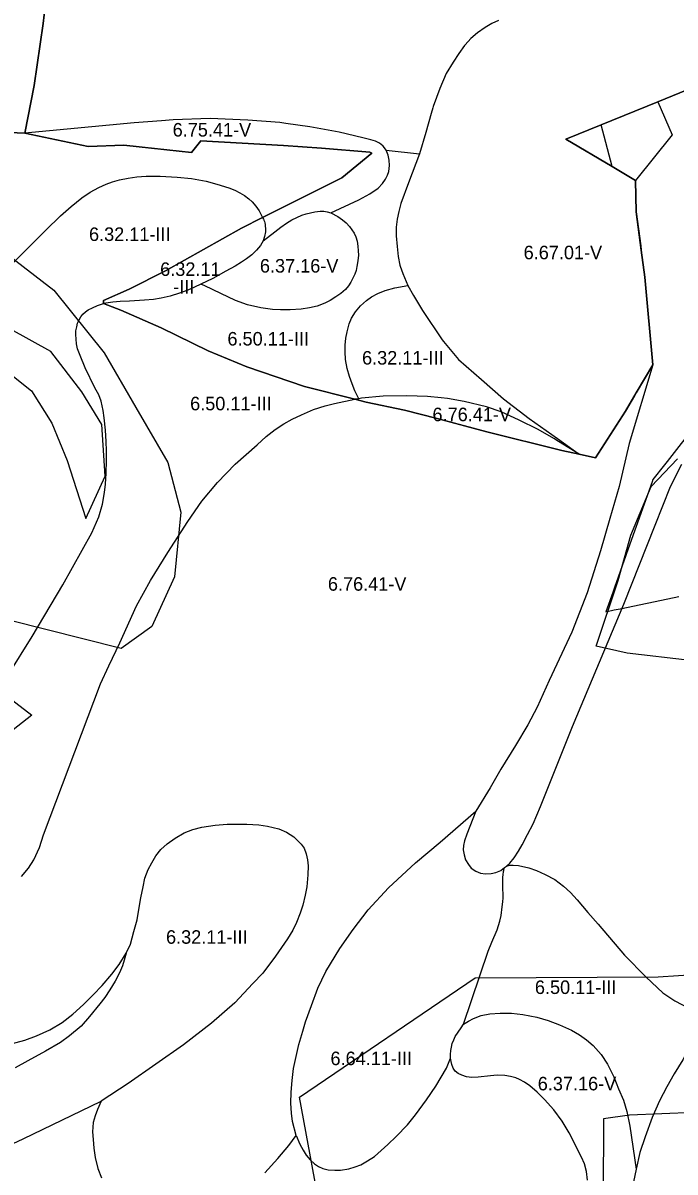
# Model space of a CAD drawing. Extents: x -555156 to -540209, y -1046851 to -1035695.
# Drawn here: x -544168 to -543686, y -1041405 to -1040556 of the extents above; entities that cross this region are included whole.
import ezdxf

# ---------------------------------------------------------------- set-up
doc = ezdxf.new("R2010")
doc.units = 0
for name, color, linetype in [('Vrstva 12', 7, 'Continuous'), ('Vrstva 27', 7, 'Continuous'), ('Vrstva 28', 7, 'Continuous'), ('Vrstva 29', 7, 'Continuous')]:
    doc.layers.add(name, color=color, linetype=linetype)

msp = doc.modelspace()

# ---------------------------------------------------------------- linework, layer by layer
at = {"layer": 'Vrstva 12'}
for points in [[(-543648.44, -1040824.55), (-543691.97, -1040880.16), (-543693.82, -1040882.53), (-543702.32, -1040893.39), (-543702.91, -1040895.06), (-543720.55, -1040944.72), (-543722.26, -1040949.53), (-543730.66, -1040973.17), (-543732.03, -1040977.02), (-543737.03, -1040991.11), (-543730.9, -1040989.84), (-543726.55, -1040988.94), (-543686.62, -1040980.68), (-543683.27, -1040979.99)], [(-543671.97, -1041361.22), (-543719.58, -1041363.23), (-543738.950827, -1041365.94664), (-543738.95, -1041369.67), (-543738.97, -1041384.97), (-543739.29, -1041421.11)]]:
    msp.add_lwpolyline(points, dxfattribs=at)
at = {"layer": 'Vrstva 28'}
for points in [[(-544166.22, -1040637.59), (-544159.37, -1040602.39), (-544152.78, -1040556.39), (-544148.25, -1040518.25), (-544148.05, -1040516.52), (-544147.1, -1040509.05), (-544119.61, -1040511.85), (-544114.36, -1040467.79), (-544109.21, -1040427.07), (-544107.28, -1040390.92), (-544084.37, -1040386.84), (-544033.06, -1040401.65), (-543986.48, -1040373.41), (-543990.67, -1040372.14), (-543961.4, -1040311.25), (-543946.79, -1040291.41)], [(-544148.45, -1040519.91), (-544152.78, -1040556.39), (-544159.37, -1040602.39), (-544166.22, -1040637.59), (-544194.81, -1040636.28)], [(-543816.51, -1040554.2), (-543821.29, -1040556.44), (-543826.22, -1040559.43), (-543831.9, -1040563.46), (-543836.83, -1040567.65), (-543840.95, -1040572.17), (-543841.46, -1040572.73), (-543845.64, -1040578.56), (-543849.97, -1040585.13), (-543855.2, -1040593.5), (-543859.83, -1040604.41), (-543864.61, -1040617.71), (-543864.93, -1040618.82), (-543866.15, -1040623.11), (-543870.1, -1040637), (-543874.8, -1040652.69)], [(-543702.42, -1040808.65), (-543708.38, -1040743.94), (-543710.96, -1040724.1), (-543714.65, -1040695.64), (-543715.21, -1040672.48), (-543732.41, -1040662.28), (-543766.58, -1040642.03), (-543740.61, -1040631.41), (-543698.83, -1040614.32), (-543593.47, -1040571.22), (-543590.56, -1040569.96), (-543587.92, -1040562.74), (-543571.38, -1040556.86), (-543563.03, -1040579.77)], [(-543593.47, -1040571.22), (-543698.83, -1040614.32), (-543740.61, -1040631.41), (-543766.58, -1040642.03), (-543732.41, -1040662.28), (-543715.21, -1040672.48), (-543714.65, -1040695.64), (-543711.4, -1040720.7), (-543710.96, -1040724.1), (-543708.38, -1040743.94), (-543702.42, -1040808.65), (-543714.73, -1040829.47), (-543715.98, -1040831.59), (-543722.63, -1040842.84), (-543744.71, -1040877.32), (-543756.76, -1040874.7)], [(-543910.66, -1040642.36), (-543916.57, -1040640.99), (-543934.09, -1040636.81), (-543955.78, -1040632.89), (-543973.45, -1040630.39), (-543978, -1040629.75), (-544001.53, -1040627.92), (-544029.5, -1040626.61), (-544056.68, -1040627.66), (-544065.45, -1040628.38), (-544085.44, -1040630.01), (-544166.22, -1040637.59)], [(-544297.7, -1040664.73), (-544298.67, -1040642.1), (-544267.15, -1040646.48), (-544246.26, -1040643.8), (-544216.62, -1040644.41), (-544194.81, -1040636.28), (-544166.22, -1040637.59)], [(-544166.22, -1040637.59), (-544119.59, -1040647.38), (-544093.27, -1040646.28), (-544043.13, -1040651.87), (-544036.41, -1040643.09), (-543975.26, -1040646.77), (-543947.29, -1040648.59), (-543911.39, -1040651.66), (-543910.01, -1040652.36), (-543932.13, -1040670.57), (-543990.72, -1040699.94)], [(-543990.71, -1040699.94), (-543932.13, -1040670.57), (-543910.01, -1040652.36), (-543911.39, -1040651.66), (-543947.29, -1040648.59), (-543975.26, -1040646.77), (-544036.41, -1040643.09), (-544043.13, -1040651.87), (-544068.2, -1040649.08), (-544093.27, -1040646.28), (-544119.59, -1040647.38), (-544166.22, -1040637.59)], [(-543899.3, -1040650.05), (-543900.69, -1040648.36), (-543901.69, -1040647.14), (-543903.46, -1040645.77), (-543904.77, -1040644.75), (-543907.24, -1040643.47), (-543910.66, -1040642.36)], [(-543940.17, -1040696.35), (-543919.71, -1040686.79), (-543911.49, -1040682.45), (-543905.28, -1040678.06), (-543902.12, -1040674.64), (-543899.9, -1040671.57), (-543898.36, -1040668.58), (-543897.51, -1040665.76), (-543896.91, -1040661.32), (-543897.08, -1040657.56), (-543897.94, -1040653.89), (-543899.3, -1040650.05)], [(-543899.3, -1040650.05), (-543874.8, -1040652.69)], [(-543874.8, -1040652.69), (-543882.91, -1040674.14), (-543888.66, -1040689.57), (-543890.15, -1040695.43), (-543891.2, -1040701.11), (-543892.09, -1040707.08), (-543892.09, -1040713.51), (-543891.35, -1040721.28), (-543890.45, -1040728.75), (-543889.26, -1040735.03), (-543888.98, -1040735.84), (-543887.17, -1040741.16), (-543883.28, -1040749.98)], [(-544176.07, -1040734.52), (-544150.81, -1040709.32), (-544139.86, -1040698.54), (-544132.11, -1040691.75), (-544124.12, -1040685.33), (-544118.06, -1040681.21), (-544111.52, -1040677.7), (-544106.32, -1040675.27), (-544101.47, -1040673.58), (-544096.39, -1040672), (-544089.97, -1040670.79), (-544083.67, -1040669.7), (-544076.65, -1040669.33), (-544066.23, -1040669.33), (-544053.88, -1040669.94), (-544043.1, -1040671.15), (-544032.32, -1040673.09), (-544024.57, -1040675.15), (-544015.61, -1040677.82), (-544011.3, -1040679.63), (-544007.49, -1040681.57), (-544003.96, -1040683.65), (-544000.85, -1040686), (-543998.36, -1040688.36), (-543995.73, -1040691.54), (-543993.31, -1040694.94), (-543990.72, -1040699.94)], [(-543990.18, -1040717.05), (-543981.69, -1040710.41), (-543977.16, -1040706.99), (-543972.91, -1040704.11), (-543969.06, -1040701.63), (-543965.5, -1040699.77), (-543961.65, -1040698.21), (-543958.38, -1040697.18), (-543955.36, -1040696.31), (-543952.19, -1040695.67), (-543948.14, -1040695.28), (-543945.41, -1040695.28), (-543943.06, -1040695.62), (-543940.17, -1040696.35)], [(-543940.17, -1040696.35), (-543935.12, -1040699.16), (-543931.54, -1040701.55), (-543928.95, -1040703.79), (-543926.41, -1040706.62), (-543924.71, -1040708.96), (-543923.1, -1040711.4), (-543921.78, -1040714.14), (-543920.81, -1040717.36), (-543920.23, -1040721.14), (-543919.99, -1040724.36), (-543919.94, -1040727.63), (-543920.33, -1040731.88), (-543921.01, -1040736.17), (-543921.61, -1040738.91), (-543922.44, -1040741.64), (-543923.95, -1040744.77), (-543925.51, -1040747.74), (-543927.17, -1040750.28), (-543929.56, -1040753.11), (-543932.83, -1040755.89), (-543936.68, -1040758.43), (-543940.73, -1040761.06), (-543944.78, -1040763.11), (-543950.3, -1040765.4), (-543956.02, -1040766.6), (-543962.17, -1040767.54), (-543970.36, -1040767.96)], [(-543990.72, -1040699.94), (-544006.25, -1040707.73), (-544062.36, -1040739.14), (-544089.23, -1040752.75), (-544108.19, -1040761.26), (-544108.27, -1040763.37)], [(-544108.27, -1040763.37), (-544108.19, -1040761.26), (-544089.23, -1040752.75), (-544062.36, -1040739.14), (-544006.25, -1040707.73), (-543990.71, -1040699.94)], [(-543990.71, -1040699.94), (-543990.13, -1040700.99), (-543989.82, -1040701.67), (-543989.71, -1040701.91), (-543989.26, -1040702.89), (-543989.04, -1040703.86), (-543988.82, -1040705.03), (-543988.68, -1040706.26), (-543988.65, -1040708), (-543988.65, -1040710.47), (-543989.24, -1040713.89), (-543990.18, -1040717.05)], [(-543990.18, -1040717.05), (-543992.15, -1040720.47), (-543995.13, -1040724.05), (-543998.55, -1040727.38), (-544002.56, -1040730.46), (-544006.27, -1040732.95), (-544010.97, -1040735.77), (-544017.8, -1040739.61), (-544027.36, -1040744.82), (-544036.21, -1040749.01)], [(-544036.21, -1040749.01), (-544040.9, -1040751.32), (-544046.02, -1040753.45), (-544052.08, -1040755.76), (-544058.91, -1040757.89), (-544065.65, -1040759.43), (-544071.29, -1040760.45), (-544077.86, -1040761.05), (-544089.04, -1040761.56), (-544095.87, -1040761.99), (-544101.25, -1040762.33)], [(-543970.36, -1040767.96), (-543977.53, -1040768.13), (-543983.42, -1040767.79), (-543991.87, -1040766.68), (-544001.77, -1040764.29), (-544010.73, -1040761.3), (-544021.57, -1040756.09), (-544033.44, -1040750.46), (-544036.21, -1040749.01)], [(-543918.25, -1040765.13), (-543913.99, -1040761.29), (-543910.23, -1040758.47), (-543905.62, -1040755.91), (-543900.16, -1040753.86), (-543893.08, -1040751.72), (-543883.28, -1040749.98)], [(-543883.28, -1040749.98), (-543879.25, -1040757.45), (-543872.68, -1040768.51), (-543857.99, -1040790.28), (-543857.15, -1040791.52), (-543845.91, -1040804.86), (-543828.92, -1040819.5)], [(-544196.12, -1041065.58), (-544160.88, -1041009.55), (-544138.26, -1040971.27), (-544116.85, -1040932.89), (-544111.56, -1040921.02), (-544108.95, -1040911.66), (-544107.5, -1040902.93), (-544106.77, -1040896.99), (-544106.17, -1040888.88), (-544105.92, -1040879.18), (-544105.92, -1040872.27), (-544106.17, -1040865.49), (-544106.65, -1040856.89), (-544107.74, -1040847.8), (-544108.35, -1040842.35), (-544109.92, -1040835.68), (-544111.62, -1040830.83), (-544114.52, -1040825.72), (-544121.65, -1040810.83), (-544125.38, -1040801.76), (-544127.32, -1040796.78), (-544128.08, -1040793.31), (-544128.5, -1040789.85), (-544128.64, -1040786.39), (-544128.64, -1040783.62), (-544128.01, -1040780.57), (-544127.32, -1040778.01), (-544126.21, -1040775.52), (-544124.97, -1040773.3), (-544123.45, -1040771.36), (-544121.58, -1040769.63), (-544119.42, -1040768.11), (-544116.27, -1040766.53), (-544112.63, -1040764.84), (-544108.27, -1040763.37)], [(-544101.25, -1040762.33), (-544108.27, -1040763.37)], [(-544108.27, -1040763.37), (-544095.39, -1040768.31)], [(-543922.54, -1040834.19), (-543959.63, -1040824.69), (-544002.2, -1040810.3), (-544030.94, -1040798.31), (-544065.53, -1040781.42), (-544095.39, -1040768.31), (-544108.27, -1040763.37)], [(-543919.6, -1040833.75), (-543920.66, -1040831.83), (-543922.5, -1040827.86), (-543924.46, -1040822.82), (-543926.51, -1040817.44), (-543928.13, -1040811.47), (-543929.33, -1040804.89), (-543929.67, -1040799.08), (-543929.61, -1040794.25), (-543929.18, -1040789.04), (-543928.24, -1040784.43), (-543926.79, -1040778.45), (-543925, -1040774.18), (-543922.01, -1040769.49), (-543918.25, -1040765.13)], [(-544095.39, -1040768.31), (-544065.53, -1040781.42), (-544030.94, -1040798.31), (-544002.2, -1040810.3), (-543959.63, -1040824.69), (-543922.49, -1040834.2)], [(-543922.49, -1040834.2), (-543914.18, -1040836.33), (-543885.98, -1040842.13), (-543861.85, -1040848.48), (-543825.12, -1040858.15), (-543769.53, -1040871.92), (-543756.76, -1040874.7), (-543744.71, -1040877.32), (-543722.63, -1040842.84), (-543714.73, -1040829.47), (-543702.42, -1040808.65)], [(-543702.42, -1040808.65), (-543719.92, -1040866.73)], [(-543828.92, -1040819.5), (-543812.71, -1040833.89), (-543793.89, -1040848.27), (-543772.96, -1040863.17), (-543756.76, -1040874.7)], [(-544168.82, -1041186.75), (-544163.61, -1041180.57), (-544159.74, -1041174.39), (-544155.5, -1041165.31), (-544152.59, -1041155.98), (-544110.4, -1041044.53), (-544104.37, -1041031.07), (-544096.1, -1041014.1), (-544083.81, -1040986.75), (-544073.43, -1040968.09), (-544060.71, -1040947.31), (-544045.88, -1040924.4), (-544035.49, -1040909.56), (-544024.05, -1040895.78), (-544010.91, -1040882.21), (-543994.8, -1040867.79), (-543987.98, -1040861.66), (-543981.32, -1040856.57), (-543974.9, -1040852.33), (-543968.85, -1040848.82), (-543962.06, -1040845.55), (-543953.1, -1040841.67), (-543944.38, -1040839), (-543937.48, -1040837.31), (-543922.49, -1040834.2)], [(-543919.6, -1040833.75), (-543922.54, -1040834.19)], [(-543756.76, -1040874.7), (-543769.53, -1040871.92), (-543825.12, -1040858.15), (-543859.1, -1040849.21), (-543861.85, -1040848.48), (-543885.98, -1040842.13), (-543914.18, -1040836.33), (-543922.54, -1040834.19)], [(-543772.11, -1040865.35), (-543775.52, -1040863.27), (-543787.17, -1040856.55), (-543801.07, -1040849.67), (-543814.36, -1040843.55), (-543825.41, -1040839.66), (-543841.84, -1040835.92), (-543854.09, -1040833.68), (-543858.8, -1040833.16), (-543868.88, -1040832.04), (-543884.11, -1040831.74), (-543901.74, -1040831.89), (-543917.64, -1040833.46), (-543919.6, -1040833.75)], [(-543719.92, -1040866.73), (-543727.34, -1040898.54), (-543734.12, -1040922.29), (-543741.11, -1040946.04), (-543750.87, -1040977.09), (-543762.32, -1041006.14), (-543779.06, -1041041.98), (-543787.96, -1041061.7), (-543794.75, -1041074.84), (-543803.92, -1041090.04), (-543814.82, -1041107.49), (-543822.57, -1041121.31), (-543833.11, -1041138.63)], [(-543756.76, -1040874.7), (-543772.11, -1040865.35)], [(-543810.54, -1041179.21), (-543808.12, -1041176.92), (-543804.93, -1041172.91), (-543801.68, -1041167.99), (-543798.91, -1041163.49), (-543795.04, -1041155.86), (-543790.92, -1041147.86), (-543785.39, -1041135.08), (-543761.66, -1041076.07), (-543723.84, -1040985.67), (-543700.74, -1040927.15), (-543689.29, -1040898.52), (-543681.03, -1040882.19)], [(-543965.9, -1041378.12), (-543968.7, -1041367.88), (-543969.43, -1041361.58), (-543969.92, -1041354.31), (-543969.55, -1041346.19), (-543968.83, -1041337.47), (-543967.74, -1041328.74), (-543965.92, -1041319.89), (-543963.86, -1041310.93), (-543961.07, -1041301.11), (-543958.89, -1041294.09), (-543954.57, -1041282.1), (-543949.91, -1041269.37), (-543943.98, -1041257.07), (-543933.59, -1041240.11), (-543923.84, -1041225.9), (-543912.61, -1041211.48), (-543897.56, -1041195.16), (-543877.85, -1041176.71), (-543859.62, -1041161.44), (-543833.11, -1041138.63)], [(-543833.11, -1041138.63), (-543839.88, -1041155.6)], [(-543993.5, -1041148.65), (-543986.96, -1041149.62), (-543978.72, -1041151.56), (-543973.03, -1041154.11), (-543967.7, -1041157.38), (-543962.13, -1041162.83), (-543960.09, -1041165.78), (-543958.43, -1041170.07), (-543957.39, -1041174.57), (-543957.05, -1041179.01), (-543957.25, -1041185.58), (-543958.02, -1041194.52), (-543959.12, -1041200.47), (-543961.06, -1041207.95), (-543963.05, -1041213.93), (-543965.71, -1041220.72), (-543968.25, -1041226.41), (-543972.25, -1041232.84), (-543981.09, -1041245.68), (-543990.54, -1041258.16), (-543997.8, -1041265.92), (-544011.13, -1041280.22), (-544028.32, -1041295.24), (-544049.2, -1041311.19), (-544089.89, -1041339.82), (-544109.81, -1041352.75)], [(-544091.46, -1041243.47), (-544088.31, -1041236.68), (-544085.77, -1041227.35), (-544083.22, -1041218.75), (-544082.03, -1041211.3), (-544080.69, -1041202.58), (-544079, -1041194.34), (-544077.55, -1041188.03), (-544075.12, -1041181.73), (-544072.58, -1041176.64), (-544069.43, -1041171.43), (-544065.8, -1041166.95), (-544061.2, -1041162.59), (-544055.38, -1041158.35), (-544048.72, -1041154.59), (-544042.3, -1041152.05), (-544035.64, -1041150.35), (-544025.83, -1041148.9), (-544016.87, -1041148.17), (-544009.73, -1041148.17), (-544002.34, -1041148.05), (-543993.5, -1041148.65)], [(-543839.88, -1041155.6), (-543841.61, -1041160.44), (-543842.37, -1041163.77), (-543842.44, -1041167.09), (-543841.89, -1041170.9), (-543840.71, -1041174.57), (-543838.71, -1041178.03), (-543836.7, -1041180.52), (-543833.24, -1041182.88), (-543829.85, -1041184.26), (-543825.97, -1041184.82), (-543821.82, -1041184.61), (-543818.5, -1041183.92), (-543814.83, -1041182.39), (-543811.92, -1041180.24)], [(-543842.17, -1041296.03), (-543823.96, -1041241.94), (-543821.4, -1041235.44), (-543817.53, -1041226.23), (-543815.52, -1041219.72), (-543814.55, -1041215.56), (-543813.65, -1041209.19), (-543813.17, -1041205.45), (-543813.04, -1041202.51), (-543813.16, -1041193.22), (-543813.12, -1041188.15), (-543812.9, -1041184.72), (-543812.82, -1041183.93), (-543812.76, -1041183.22), (-543812.61, -1041182.46), (-543812.45, -1041181.71), (-543812.27, -1041181.01), (-543811.92, -1041180.24)], [(-543811.92, -1041180.24), (-543810.54, -1041179.21)], [(-543810.54, -1041179.21), (-543809.67, -1041178.86), (-543808.93, -1041178.62), (-543808.19, -1041178.47), (-543807.49, -1041178.38), (-543806.6, -1041178.31), (-543805.56, -1041178.33)], [(-543805.56, -1041178.33), (-543801.54, -1041178.79), (-543794.15, -1041180.49), (-543788.46, -1041182.31), (-543781.92, -1041185.21), (-543774.9, -1041189.09), (-543768.48, -1041193.94), (-543763.27, -1041198.54), (-543758.31, -1041204), (-543750.56, -1041213.33), (-543742.85, -1041221.98), (-543723.35, -1041244.88), (-543707.45, -1041261.21), (-543695.16, -1041272.66), (-543686.26, -1041278.59), (-543675.24, -1041284.32), (-543662.75, -1041290.03)], [(-544179.12, -1041311.23), (-544166.41, -1041307.71), (-544157.57, -1041304.44), (-544147.76, -1041300.08), (-544138.8, -1041294.63), (-544130.92, -1041288.57), (-544122.93, -1041281.3), (-544115.92, -1041274.13), (-544109.26, -1041267.34), (-544102.11, -1041258.98), (-544096.54, -1041251.83), (-544091.46, -1041243.47)], [(-544091.46, -1041243.47), (-544093.01, -1041248.71), (-544094.18, -1041252.79), (-544096.33, -1041258.06), (-544099.65, -1041264.22), (-544103.6, -1041270.59), (-544107.33, -1041276.13), (-544110.79, -1041280.99), (-544118.42, -1041290.32), (-544124.72, -1041297.35), (-544133.2, -1041304.5), (-544140.05, -1041309.44), (-544150.95, -1041315.86), (-544164.16, -1041323.01), (-544173.48, -1041328.1)], [(-543842.17, -1041296.03), (-543838.6, -1041293.6), (-543834.96, -1041291.66), (-543829.15, -1041289.6), (-543822.85, -1041288.39), (-543815.1, -1041287.9), (-543806.74, -1041287.78), (-543798.39, -1041288.75)], [(-543798.39, -1041288.75), (-543788.09, -1041290.69), (-543779.74, -1041293.11), (-543771.26, -1041296.38), (-543762.54, -1041300.38), (-543756.61, -1041303.9), (-543751.52, -1041307.53), (-543746.55, -1041311.65), (-543740.5, -1041318.2), (-543735.9, -1041325.47), (-543731.29, -1041334.8), (-543727.69, -1041343.64), (-543724.06, -1041352), (-543721.76, -1041360.49), (-543719.34, -1041371.39), (-543714.76, -1041402.93)], [(-543662.75, -1041290.03), (-543673.29, -1041310.02), (-543680.19, -1041322.38), (-543686.61, -1041332.56), (-543691.99, -1041342.1), (-543697.44, -1041352.64), (-543703.01, -1041364.76), (-543708.22, -1041379.06), (-543712.09, -1041390.81), (-543714.76, -1041402.93)], [(-543851.78, -1041320.96), (-543851.78, -1041318.32), (-543851.71, -1041315.49), (-543851.23, -1041312.79), (-543850.54, -1041310.29), (-543849.5, -1041307.52), (-543848.32, -1041305.03), (-543846.24, -1041301.91), (-543844.1, -1041298.66), (-543842.17, -1041296.03)], [(-543965.9, -1041378.12), (-543963.26, -1041384.64), (-543960.71, -1041389), (-543958.41, -1041392.75), (-543955.44, -1041396.1), (-543952.39, -1041399.14), (-543949.49, -1041401.15), (-543946.1, -1041402.6), (-543942.15, -1041403.44), (-543937.38, -1041403.85), (-543933.09, -1041403.85), (-543927.06, -1041402.88), (-543922.29, -1041401.43), (-543918.07, -1041399.77), (-543913.29, -1041397), (-543908.1, -1041393.67), (-543903.19, -1041389.38), (-543898.14, -1041384.81), (-543892.12, -1041378.99), (-543883.67, -1041370.2), (-543877.64, -1041362.89), (-543869.53, -1041351.86), (-543862.63, -1041341.68), (-543854.75, -1041328.36), (-543851.78, -1041320.96)], [(-543750.69, -1041411.08), (-543751.53, -1041404.78), (-543752.99, -1041399.09), (-543755.02, -1041394.3), (-543764.34, -1041376.12), (-543769.31, -1041367.52), (-543775.62, -1041359.23), (-543782.54, -1041351.61), (-543787.87, -1041346.07), (-543793.34, -1041341.57), (-543797.14, -1041338.87), (-543800.81, -1041336.86), (-543803.75, -1041335.64), (-543807.49, -1041334.53), (-543811.78, -1041333.9), (-543817.52, -1041333.7), (-543822.44, -1041334.04), (-543831.37, -1041335.15), (-543836.21, -1041335.29), (-543840.09, -1041334.74), (-543843.41, -1041333.63), (-543846.18, -1041332.38), (-543848.39, -1041330.65), (-543849.84, -1041328.5), (-543851.02, -1041325.66), (-543851.43, -1041323.38), (-543851.78, -1041320.96)], [(-544174.87, -1041384.12), (-544167.46, -1041380.74), (-544109.81, -1041352.75)], [(-544109.81, -1041352.75), (-544112.69, -1041358.97), (-544114.38, -1041363.58), (-544115.71, -1041368.67), (-544116.2, -1041375.45), (-544115.83, -1041381.03), (-544115.23, -1041387.45), (-544114.26, -1041394.48), (-544112.32, -1041402.6), (-544109.78, -1041409.38)], [(-543988.91, -1041405.75), (-543979.47, -1041395.2), (-543971.35, -1041385.63), (-543965.9, -1041378.12)], [(-543714.76, -1041402.93), (-543716.82, -1041412.38), (-543718.27, -1041422.92), (-543719.53, -1041435.5), (-543720.37, -1041443.98), (-543720.25, -1041451.25), (-543718.92, -1041465.19), (-543717.71, -1041474.16), (-543715.17, -1041488.79), (-543710.44, -1041511.33), (-543708.5, -1041527.81), (-543708.63, -1041534.71), (-543709.59, -1041540.29), (-543711.41, -1041545.86), (-543713.59, -1041549.86), (-543716.89, -1041554.8)]]:
    msp.add_lwpolyline(points, dxfattribs=at)
at = {"layer": 'Vrstva 29'}
for points in [[(-544148.45, -1040519.91), (-544152.78, -1040556.39), (-544159.37, -1040602.39), (-544166.22, -1040637.59), (-544194.81, -1040636.28)], [(-543725.52, -1040625.24), (-543698.83, -1040614.32), (-543688.05, -1040638.79), (-543715.21, -1040672.48), (-543732.41, -1040662.28), (-543740.61, -1040631.41), (-543725.52, -1040625.24)], [(-544195.877991, -1040714.437988), (-544144.943909, -1040753.474976), (-544107.731018, -1040799.867004), (-544084.255981, -1040840.35498), (-544060.781006, -1040880.84198), (-544050.98291, -1040917.471008), (-544055.796997, -1040965.447998), (-544072.554993, -1041002.083984), (-544095.031982, -1041018.288025), (-544178.070984, -1040997.335999)], [(-544121.143005, -1040922.22699), (-544106.937012, -1040890.955017), (-544109.434021, -1040852.72998), (-544124.250977, -1040828.622986), (-544147.216003, -1040798.890991), (-544176.791016, -1040782.292908), (-544237.250977, -1040754.835999), (-544236.153015, -1040791.651978), (-544209.339905, -1040802.375977), (-544182.10498, -1040811.356995), (-544161.458984, -1040827.86499), (-544146.364014, -1040851.744019), (-544134.943909, -1040879.351013), (-544121.143005, -1040922.22699)], [(-543674.817993, -1041027.158997), (-543721.281006, -1041021.692017), (-543744.296997, -1041016.684021), (-543727.927979, -1040968.028992), (-543718.61499, -1040934.504028), (-543703.723999, -1040898.708984), (-543684.151978, -1040878.14801)], [(-544208.60199, -1041031.124023), (-544161.247009, -1041067.525024), (-544271.908997, -1041154.570984)], [(-543950.567993, -1041419.36499), (-543963.367004, -1041349.817017), (-543833.716003, -1041261.783997), (-543698.562012, -1041260.956909), (-543623.521912, -1041255.903992)]]:
    msp.add_lwpolyline(points, dxfattribs=at)

# ---------------------------------------------------------------- texts
at = {"layer": 'Vrstva 27'}
for s, p in [('6.75.41-V', (-544057.101006, -1040640.02)), ('6.32.11-III', (-544118.896548, -1040717.2)), ('6.67.01-V', (-543797.861006, -1040730.7)), ('6.37.16-V', (-543992.667974, -1040740.54)), ('6.32.11', (-544066.337261, -1040743.01)), ('-III', (-544056.732769, -1040756.01)), ('6.50.11-III', (-544016.636548, -1040794.45)), ('6.32.11-III', (-543917.226548, -1040808.52)), ('6.50.11-III', (-544044.216548, -1040842.33)), ('6.76.41-V', (-543865.181006, -1040850.37)), ('6.76.41-V', (-543942.431006, -1040975.62)), ('6.32.11-III', (-544062.006548, -1041236.5)), ('6.50.11-III', (-543789.536548, -1041273.61)), ('6.64.11-III', (-543940.526548, -1041326.2)), ('6.37.16-V', (-543787.437974, -1041344.82))]:
    msp.add_text(s, height=10, dxfattribs=at).set_placement(p)

doc.saveas('drawing.dxf')
